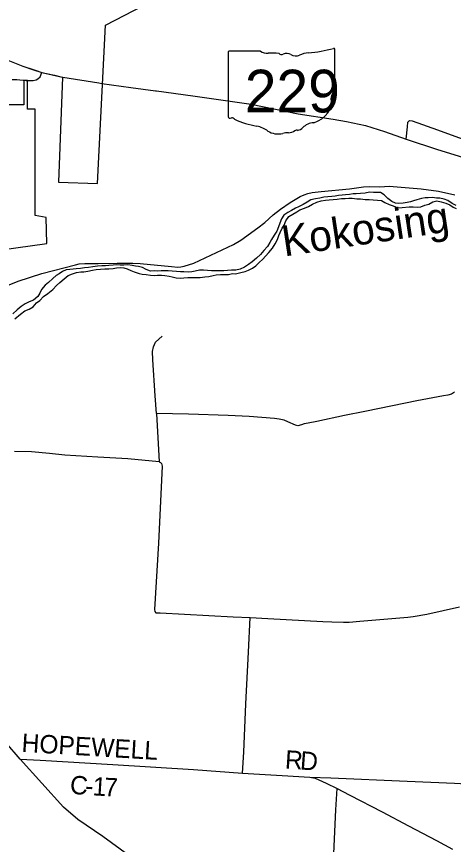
# Model space of a CAD drawing. Extents: x 41.3 to 81.6, y -19.3 to 2.7.
# Drawn here: x 44.697 to 45.839, y -1.162 to 1 of the extents above; entities that cross this region are included whole.
import ezdxf

# ---------------------------------------------------------------- set-up
doc = ezdxf.new("R2010")
doc.units = 0
for name, color, linetype in [('GM_X_Corporation', 7, 'Continuous'), ('GM_X_County_Road', 7, 'Continuous'), ('GM_X_County_Road_Text', 7, 'Continuous'), ('GM_X_Major_River', 7, 'Continuous'), ('GM_X_Major_River_Text', 7, 'Continuous'), ('GM_X_State_Route', 7, 'Continuous'), ('GM_X_State_Shield', 7, 'Continuous'), ('GM_X_Township_Road', 7, 'Continuous')]:
    doc.layers.add(name, color=color, linetype=linetype)

msp = doc.modelspace()

# ---------------------------------------------------------------- linework, layer by layer
at = {"layer": 'GM_X_Corporation'}
for points in [[(44.6697, 0.8884), (44.7134, 0.8708), (44.7412, 0.8615), (44.7634, 0.8542), (44.8177, 0.842), (44.8069, 0.5678), (44.9086, 0.564), (44.9296, 0.9782), (45.0293, 1.0296)], [(44.5383, 0.3743), (44.776, 0.4078), (44.7746, 0.4758), (44.7463, 0.4805), (44.7463, 0.7585), (44.7255, 0.7585), (44.7255, 0.8337), (44.7163, 0.8342), (44.7163, 0.7696), (44.6523, 0.7696)]]:
    msp.add_lwpolyline(points, dxfattribs=at)
at = {"layer": 'GM_X_County_Road'}
msp.add_lwpolyline([(44.7068, -0.9396), (44.759, -0.942), (44.9488, -0.9536), (45.1601, -0.9665), (45.2875, -0.9765), (45.3915, -0.9825), (45.4641, -0.987), (45.4782, -0.9891), (45.5066, -1.0026), (45.5352, -1.0164), (45.5502, -1.0239), (45.5686, -1.0335), (45.653, -1.0775), (45.722, -1.1133), (45.7949, -1.1524), (45.8366, -1.1747)], dxfattribs=at)
at = {"layer": 'GM_X_Major_River'}
for points in [[(45.6488, 0.5408), (45.6382, 0.5411), (45.6302, 0.5411), (45.6199, 0.5418), (45.609, 0.5389), (45.5968, 0.5379), (45.5849, 0.537), (45.5769, 0.537), (45.5676, 0.5354), (45.557, 0.5347), (45.5483, 0.5341), (45.5387, 0.5325), (45.5303, 0.5309), (45.5217, 0.5302), (45.5108, 0.5296), (45.5008, 0.5283), (45.4899, 0.5261), (45.4786, 0.5241), (45.4668, 0.5213), (45.4568, 0.5158), (45.4462, 0.5091), (45.4346, 0.5033), (45.4266, 0.4994), (45.416, 0.4933), (45.4064, 0.4882), (45.3961, 0.4811), (45.3897, 0.4722), (45.3852, 0.4609), (45.3823, 0.4506), (45.3778, 0.4397), (45.371, 0.4291), (45.364, 0.4179), (45.3598, 0.4099), (45.3534, 0.3996), (45.344, 0.3893), (45.3347, 0.3788), (45.3244, 0.3691), (45.3135, 0.3592), (45.3036, 0.3524), (45.2933, 0.3457), (45.2814, 0.3402), (45.2702, 0.3374), (45.2589, 0.3374), (45.2487, 0.337), (45.2387, 0.3364), (45.2303, 0.3361), (45.2188, 0.3358), (45.2072, 0.3361), (45.1963, 0.337), (45.186, 0.3377), (45.1751, 0.3377), (45.1639, 0.3351), (45.1555, 0.3335), (45.1456, 0.3329), (45.1347, 0.3332), (45.126, 0.3335), (45.1151, 0.3345), (45.1045, 0.3348), (45.0939, 0.3361), (45.0833, 0.3364), (45.0749, 0.3364), (45.0669, 0.3355), (45.0586, 0.3361), (45.0473, 0.3348), (45.0364, 0.3396), (45.0261, 0.3451), (45.0162, 0.347), (45.0078, 0.3486), (44.9995, 0.3499), (44.9879, 0.3519), (44.978, 0.3509), (44.968, 0.3509), (44.9593, 0.3515), (44.9494, 0.3512), (44.9385, 0.3499), (44.9301, 0.3493), (44.9205, 0.3493), (44.9089, 0.3483), (44.8971, 0.3464), (44.8855, 0.3451), (44.8752, 0.3438), (44.8643, 0.3419), (44.8531, 0.3416), (44.845, 0.3403), (44.8367, 0.34), (44.827, 0.3387), (44.8174, 0.3345), (44.8084, 0.3281), (44.8004, 0.3243), (44.7917, 0.3163), (44.7811, 0.306), (44.7724, 0.2983), (44.7628, 0.2877), (44.7583, 0.2774), (44.7532, 0.2688), (44.7416, 0.2594), (44.7304, 0.2553), (44.7201, 0.2495), (44.7092, 0.2428), (44.6986, 0.2338), (44.6876, 0.2235)], [(45.8463, 0.5064), (45.836, 0.5119), (45.8251, 0.5196), (45.8152, 0.5231), (45.8039, 0.5263), (45.7949, 0.5263), (45.7843, 0.5273), (45.7737, 0.5267), (45.7651, 0.5267), (45.7561, 0.5254), (45.7439, 0.5219), (45.7349, 0.519), (45.7269, 0.5164), (45.7182, 0.5148), (45.7079, 0.5132), (45.697, 0.5116), (45.6883, 0.5129), (45.6784, 0.5174), (45.6675, 0.5251), (45.6585, 0.535), (45.6488, 0.5408)], [(44.7075, 0.2232), (44.7188, 0.2312), (44.73, 0.2363), (44.7409, 0.2424), (44.749, 0.2524), (44.7583, 0.2588), (44.7679, 0.2691), (44.7792, 0.2771), (44.7917, 0.2877), (44.802, 0.2976), (44.8107, 0.3053), (44.8213, 0.3153), (44.8322, 0.3243), (44.8434, 0.3284), (44.8537, 0.3313), (44.8649, 0.3333), (44.8733, 0.3339), (44.8839, 0.3355), (44.8954, 0.3374), (44.9057, 0.3393), (44.9282, 0.3413), (44.9385, 0.3413), (44.9497, 0.3419), (44.9587, 0.3438), (44.9696, 0.3445), (44.9776, 0.3438), (44.9863, 0.3409), (44.9963, 0.3368), (45.0043, 0.3332), (45.0175, 0.3291), (45.0258, 0.3278), (45.0358, 0.3262), (45.0476, 0.3246), (45.0573, 0.3239), (45.0659, 0.3246), (45.0765, 0.3245), (45.0846, 0.3239), (45.0958, 0.3223), (45.1038, 0.3204), (45.1147, 0.3181), (45.1263, 0.3172), (45.1343, 0.3178), (45.1449, 0.3184), (45.1562, 0.3191), (45.1684, 0.3184), (45.177, 0.3191), (45.1892, 0.32), (45.2002, 0.3216), (45.2111, 0.3242), (45.2191, 0.3255), (45.2303, 0.3268), (45.2416, 0.3261), (45.2509, 0.3264), (45.2615, 0.3293), (45.2698, 0.3286), (45.2833, 0.3316), (45.2949, 0.3341), (45.3032, 0.338), (45.3142, 0.3434), (45.3225, 0.3492), (45.3318, 0.3576), (45.3408, 0.3662), (45.3482, 0.3746), (45.3569, 0.3842), (45.3662, 0.3951), (45.3736, 0.407), (45.3791, 0.4182), (45.3826, 0.4285), (45.3861, 0.4365), (45.3913, 0.4474), (45.3967, 0.4558), (45.4016, 0.4667), (45.4093, 0.4783), (45.4199, 0.4837), (45.4301, 0.4901), (45.4382, 0.4953), (45.4497, 0.4994), (45.4607, 0.5042), (45.4713, 0.51), (45.4822, 0.5152), (45.4934, 0.5187), (45.5047, 0.5203), (45.5143, 0.5212), (45.5246, 0.5222), (45.5352, 0.5235), (45.5464, 0.5248), (45.5564, 0.5248), (45.566, 0.5261), (45.5743, 0.5261), (45.5869, 0.5238), (45.5965, 0.5238), (45.6087, 0.5225), (45.619, 0.5225), (45.6299, 0.5219), (45.6411, 0.5206), (45.6514, 0.5196), (45.6601, 0.5148), (45.671, 0.5097), (45.6819, 0.5058), (45.694, 0.5008), (45.7057, 0.5018)], [(45.7057, 0.5018), (45.724, 0.5032), (45.7342, 0.5029), (45.7458, 0.5023), (45.7538, 0.5036), (45.7644, 0.5077), (45.775, 0.5106), (45.7853, 0.5164), (45.7956, 0.5186), (45.8074, 0.5161), (45.8196, 0.5132), (45.8302, 0.5084), (45.8383, 0.5023), (45.8466, 0.4987)], [(44.6929, 0.2105), (44.7075, 0.2232)]]:
    msp.add_lwpolyline(points, dxfattribs=at)
at = {"layer": 'GM_X_State_Route'}
for points in [[(44.5045, 0.9828), (44.5145, 0.9764), (44.5223, 0.9693), (44.5526, 0.9487), (44.5719, 0.9359), (44.6162, 0.9128), (44.6411, 0.9001), (44.6697, 0.8884), (44.7134, 0.8708), (44.7405, 0.8618)], [(44.7405, 0.8618), (44.7483, 0.8592), (44.7634, 0.8542), (44.7963, 0.8468)], [(44.7963, 0.8468), (44.8128, 0.8431)], [(44.8128, 0.8431), (44.8185, 0.8419), (44.9127, 0.8269)], [(44.9127, 0.8269), (44.9199, 0.8258), (44.9962, 0.8154)], [(44.9962, 0.8154), (45.0607, 0.8066), (45.0631, 0.8063)], [(45.0631, 0.8063), (45.1584, 0.7933), (45.3102, 0.7711), (45.4331, 0.746), (45.5246, 0.7325), (45.5596, 0.7265), (45.6098, 0.7155), (45.6595, 0.7002), (45.7158, 0.6801), (45.7981, 0.6534), (45.8972, 0.6223)], [(44.7068, -0.9396), (44.6692, -0.8956), (44.5784, -0.8008), (44.5037, -0.7185), (44.4615, -0.6683), (44.4412, -0.6461), (44.4291, -0.6383), (44.395, -0.6202), (44.2655, -0.5593), (44.2085, -0.5351), (44.1204, -0.4949), (44.0914, -0.4774), (44.0672, -0.4635), (44.0214, -0.4371), (43.9975, -0.4234), (43.9581, -0.4039), (43.9496, -0.4004)], [(44.9912, -1.1909), (44.9227, -1.1416), (44.8578, -1.0968), (44.8201, -1.065), (44.7068, -0.9396)]]:
    msp.add_lwpolyline(points, dxfattribs=at)
at = {"layer": 'GM_X_State_Shield'}
for p, q in [((45.335, 0.9101), (45.2534, 0.9101)), ((45.5291, 0.8258), (45.5291, 0.9143)), ((45.2507, 0.9072), (45.2507, 0.7381)), ((45.5291, 0.8259), (45.5291, 0.8258))]:
    msp.add_line(p, q, dxfattribs=at)
for centre, major_axis, start_param, end_param in [((45.2539, 0.9075), (0.00323, 0), 1.712693, 3.28349), ((45.3544, 0.9297), (0.0313, 0), 4.042523, 4.731795), ((45.4299, 1.1406), (0.2953, 0), 4.814394, 5.042369), ((45.526, 0.9147), (0.0031, 0), 6.141152, 7.989035), ((45.3648, 0.8152), (0.1123, 0), 1.404758, 1.657858), ((45.3903, 0.9084), (0.00903, 0), 3.836095, 5.185415), ((45.4035, 0.8889), (0.0188, 0), 0.950623, 2.079405), ((45.4277, 0.9157), (0.0226, 0), 4.081561, 5.145723), ((45.4676, 0.8585), (0.0594, 0), 1.699011, 2.107814), ((45.5284, 0.8194), (0.0048, 0), 1.883978, 3.671073), ((45.5258, 0.8255), (0.00332, 0), 5.05454, 6.418171), ((45.5402, 0.7888), (0.021, 0), 2.387724, 3.262537), ((45.4979, 0.8082), (0.0288, 0), 5.934695, 6.695948), ((45.4465, 0.7776), (0.0739, 0), 5.101752, 6.440018), ((45.2539, 0.7378), (0.00325, 0), 3.00124, 4.508301), ((45.2544, 0.7551), (0.0248, 0), 4.665946, 4.897461), ((45.2595, 0.7284), (0.00895, 0), 0.519207, 1.627899), ((45.3725, 0.8803), (0.2132, 0), 4.195997, 4.488961), ((45.309, 0.6622), (0.0667, 0), 0.823519, 1.323587), ((45.4776, 0.6907), (0.0404, 0), 1.647645, 2.488434), ((45.3811, 0.7275), (0.0423, 0), 4.026481, 4.996735), ((45.4056, 0.6691), (0.0348, 0), 1.495662, 1.94098), ((45.4087, 0.7149), (0.0226, 0), 4.691044, 5.507374), ((45.4291, 0.6985), (0.00635, 0), 1.147584, 2.315152), ((45.4264, 0.7217), (0.0239, 0), 4.937069, 5.64225)]:
    msp.add_ellipse(centre, major_axis=major_axis, ratio=0.8, start_param=start_param, end_param=end_param, dxfattribs=at)
at = {"layer": 'GM_X_Township_Road'}
for points in [[(44.6855, 0.8356), (44.698, 0.8355), (44.7222, 0.8337), (44.7407, 0.8336), (44.7484, 0.835), (44.7533, 0.8378), (44.7594, 0.8432), (44.7634, 0.8542)], [(45.7158, 0.6801), (45.7193, 0.7125), (45.7203, 0.7245), (45.7248, 0.7287), (45.7315, 0.728), (45.7975, 0.7044), (45.9196, 0.6602)], [(44.678, 0.2997), (44.7013, 0.309), (44.763, 0.329), (44.851, 0.3521), (44.8607, 0.3541), (44.8758, 0.355), (44.9107, 0.3554), (44.9607, 0.3561), (45.0014, 0.356), (45.02, 0.3552), (45.1024, 0.3477), (45.1191, 0.346), (45.1268, 0.3462), (45.1351, 0.3479), (45.1606, 0.3562), (45.2641, 0.4049), (45.2832, 0.416), (45.3283, 0.4485), (45.3459, 0.4622), (45.3685, 0.4827), (45.3875, 0.4973), (45.4126, 0.5147), (45.4386, 0.53), (45.4493, 0.5349), (45.459, 0.5382), (45.4703, 0.5408), (45.4937, 0.5437), (45.5676, 0.5505), (45.6039, 0.5557), (45.62, 0.5563), (45.6472, 0.5556), (45.6714, 0.5569), (45.7547, 0.55), (45.8, 0.5445), (45.8434, 0.5345)], [(45.0628, -0.0363), (45.0599, 0.0096), (45.0533, 0.1037), (45.0526, 0.1252), (45.0549, 0.1374), (45.0602, 0.1495), (45.078, 0.1656)], [(45.8425, 0.0195), (45.8346, 0.0139), (45.825, 0.0114), (45.8138, 0.0094), (45.7436, -0.0036), (45.646, -0.0232), (45.6075, -0.0311), (45.5549, -0.042), (45.4826, -0.0572), (45.4595, -0.062), (45.4493, -0.0638), (45.4419, -0.066), (45.4329, -0.0684), (45.4262, -0.0674), (45.4061, -0.0585), (45.3966, -0.0542), (45.3838, -0.0515), (45.372, -0.05), (45.3051, -0.0441), (45.2504, -0.0421), (45.1464, -0.0386), (45.0628, -0.0363), (45.07, -0.1631)], [(45.07, -0.1631), (44.9884, -0.1554), (44.9097, -0.151), (44.8236, -0.1454), (44.7835, -0.1412), (44.7366, -0.1365), (44.692, -0.1355)], [(45.07, -0.1631), (45.0738, -0.1644), (45.076, -0.1673), (45.0776, -0.1741), (45.0685, -0.3751), (45.0575, -0.5489), (45.0587, -0.554), (45.0616, -0.5569), (45.0728, -0.5577), (45.2635, -0.5674), (45.3076, -0.5696), (45.3544, -0.5718), (45.4983, -0.5796), (45.5217, -0.5812), (45.5521, -0.5819), (45.5671, -0.5818), (45.5944, -0.5792), (45.72, -0.5689), (45.7338, -0.5671), (45.7701, -0.5608), (45.8549, -0.542)], [(45.2875, -0.9765), (45.2911, -0.921), (45.297, -0.795), (45.3037, -0.66), (45.3076, -0.5696)], [(45.4641, -0.987), (45.5186, -0.988), (45.7183, -0.9968)], [(45.5017, -1.675), (45.5047, -1.6605), (45.5058, -1.6493), (45.5082, -1.6025), (45.5126, -1.5165), (45.5148, -1.4573), (45.5177, -1.3989), (45.5251, -1.2241), (45.532, -1.0718), (45.5352, -1.0164)], [(45.7183, -0.9968), (45.8423, -1.0023), (46.3278, -1.0295), (46.8046, -1.0557), (46.892, -1.0615), (46.8967, -1.0581), (46.8974, -1.0547)]]:
    msp.add_lwpolyline(points, dxfattribs=at)

# ---------------------------------------------------------------- texts
at = {"layer": 'GM_X_County_Road_Text'}
for s, rotation, p in [('HOPEWELL', 356.5665, (44.7095, -0.9202)), ('R', 356.4069, (45.398, -0.9639)), ('D', 355.7633, (45.4372, -0.9664)), ('C', 356.2428, (44.8359, -1.03)), ('1', 356.421, (44.8951, -1.0339)), ('7', 357.2483, (44.9254, -1.0358)), ('-', 356.2664, (44.8753, -1.0326))]:
    msp.add_text(s, height=0.048, rotation=rotation, dxfattribs=at).set_placement(p)
at = {"layer": 'GM_X_Major_River_Text'}
msp.add_text('Kokosing', height=0.08, rotation=8.6002, dxfattribs=at).set_placement((45.3971, 0.3734))
at = {"layer": 'GM_X_State_Shield'}
msp.add_text('229', height=0.11138, dxfattribs=at).set_placement((45.2939, 0.75))

doc.saveas('drawing.dxf')
